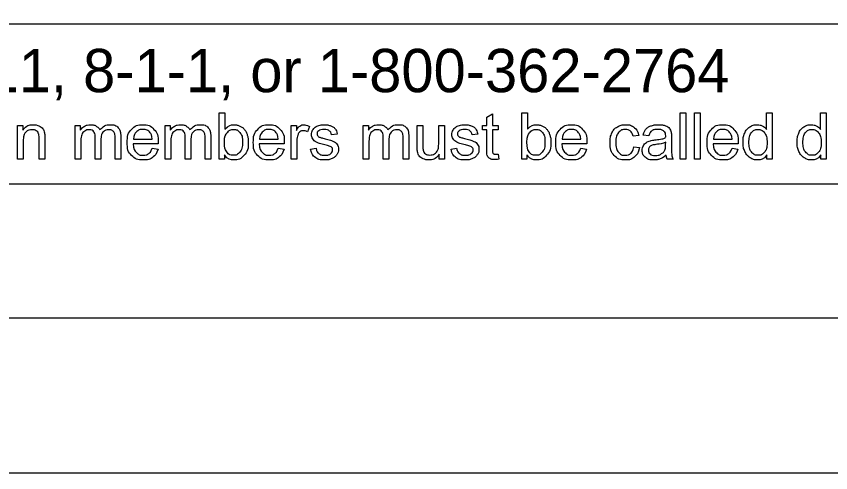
# Model space of a CAD drawing. Extents: x -1.2 to 34, y -8.5 to 22.
# Drawn here: x 15.565 to 18.2, y 0 to 1.476 of the extents above; entities that cross this region are included whole.
import ezdxf

# ---------------------------------------------------------------- set-up
doc = ezdxf.new("R2010")
doc.units = 0
for name, color, linetype in [('SH_Border', 7, 'Continuous'), ('SH_Cut_Line', 7, 'Continuous'), ('SH_Data', 7, 'Continuous'), ('SH_Text', 7, 'Continuous')]:
    doc.layers.add(name, color=color, linetype=linetype)

msp = doc.modelspace()

# ---------------------------------------------------------------- linework, layer by layer
at = {"layer": 'SH_Border'}
msp.add_lwpolyline([(1.5, 21.5), (33.5, 21.5), (33.5, 0.5), (1.5, 0.5)], close=True, dxfattribs=at)
at = {"layer": 'SH_Cut_Line'}
msp.add_lwpolyline([(0, 0), (34, 0), (34, 22), (0, 22)], close=True, dxfattribs=at)
at = {"layer": 'SH_Data'}
for p, q in [((19.0916, 1.4506), (14.8416, 1.4506)), ((19.0916, 0.9328), (14.8416, 0.9328))]:
    msp.add_line(p, q, dxfattribs=at)
at = {"layer": 'SH_Text'}
for points in [[(16.2384, 1.0139), (16.2214, 1.0139), (16.2214, 1.164), (16.2398, 1.164), (16.2398, 1.1105)], [(17.0874, 1.0457), (17.0874, 1.1084), (17.0737, 1.1084), (17.0737, 1.1227), (17.0874, 1.1227), (17.0874, 1.1497), (17.1058, 1.1607), (17.1058, 1.1227), (17.1242, 1.1227), (17.1242, 1.1084), (17.1058, 1.1084), (17.1058, 1.0447)], [(17.2175, 1.0139), (17.2004, 1.0139), (17.2004, 1.164), (17.2189, 1.164), (17.2189, 1.1105)], [(17.7131, 1.0139), (17.7131, 1.164), (17.7316, 1.164), (17.7316, 1.0139), (17.7131, 1.0139)], [(17.7597, 1.0139), (17.7597, 1.164), (17.7781, 1.164), (17.7781, 1.0139), (17.7597, 1.0139)], [(17.9926, 1.1102), (17.9926, 1.164), (18.011, 1.164), (18.011, 1.0139), (17.994, 1.0139)], [(18.1675, 1.1102), (18.1675, 1.164), (18.1859, 1.164), (18.1859, 1.0139), (18.1689, 1.0139)], [(15.5689, 1.0139), (15.5689, 1.1227), (15.5855, 1.1227), (15.5855, 1.1073)], [(15.7553, 1.0139), (15.7553, 1.1227), (15.7718, 1.1227), (15.7718, 1.1074)], [(16.0467, 1.0139), (16.0467, 1.1227), (16.0632, 1.1227), (16.0632, 1.1074)], [(16.4545, 1.0139), (16.4545, 1.1227), (16.4711, 1.1227), (16.4711, 1.1062)], [(16.5135, 1.1192), (16.5071, 1.1022)], [(16.6877, 1.0139), (16.6877, 1.1227), (16.7042, 1.1227), (16.7042, 1.1074)], [(16.862, 1.0553), (16.862, 1.1227), (16.8804, 1.1227), (16.8804, 1.0624)], [(16.9317, 1.0645), (16.9317, 1.1227), (16.9501, 1.1227), (16.9501, 1.0139), (16.9337, 1.0139)], [(15.6573, 1.0808), (15.6573, 1.0139), (15.6388, 1.0139), (15.6388, 1.08)], [(15.8384, 1.0771), (15.8384, 1.0139), (15.82, 1.0139), (15.82, 1.0845)], [(15.9028, 1.0886), (15.9028, 1.0139), (15.8844, 1.0139), (15.8844, 1.0824)], [(16.1298, 1.0771), (16.1298, 1.0139), (16.1114, 1.0139), (16.1114, 1.0845)], [(16.1942, 1.0886), (16.1942, 1.0139), (16.1758, 1.0139), (16.1758, 1.0824)], [(16.6035, 1.0946), (16.5854, 1.0922)], [(16.7708, 1.0771), (16.7708, 1.0139), (16.7524, 1.0139), (16.7524, 1.0845)], [(16.8352, 1.0886), (16.8352, 1.0139), (16.8168, 1.0139), (16.8168, 1.0824)], [(17.0581, 1.0946), (17.04, 1.0922)], [(17.5795, 1.0907), (17.5615, 1.0879)], [(17.612, 1.0892), (17.5939, 1.0916)], [(17.685, 1.084), (17.685, 1.0595)], [(15.5873, 1.0733), (15.5873, 1.0139), (15.5689, 1.0139)], [(15.7738, 1.0703), (15.7738, 1.0139), (15.7553, 1.0139)], [(16.0241, 1.0636), (15.9429, 1.0636)], [(15.944, 1.0787), (16.0047, 1.0787)], [(16.0651, 1.0703), (16.0651, 1.0139), (16.0467, 1.0139)], [(16.4321, 1.0636), (16.3509, 1.0636)], [(16.3519, 1.0787), (16.4127, 1.0787)], [(16.4729, 1.0709), (16.4729, 1.0139), (16.4545, 1.0139)], [(16.7061, 1.0703), (16.7061, 1.0139), (16.6877, 1.0139)], [(17.4111, 1.0636), (17.33, 1.0636)], [(17.331, 1.0787), (17.3918, 1.0787)], [(17.6663, 1.0617), (17.6664, 1.0685)], [(17.9007, 1.0636), (17.8196, 1.0636)], [(17.8206, 1.0787), (17.8814, 1.0787)], [(16.0045, 1.049), (16.0236, 1.0466)], [(16.4125, 1.049), (16.4316, 1.0466)], [(16.5171, 1.0464), (16.5353, 1.0492)], [(16.9337, 1.0139), (16.9337, 1.0299)], [(16.9717, 1.0464), (16.9899, 1.0492)], [(17.1242, 1.0303), (17.1268, 1.014)], [(17.3916, 1.049), (17.4106, 1.0466)], [(17.5631, 1.0537), (17.5812, 1.0513)], [(17.8812, 1.049), (17.9002, 1.0466)], [(16.2384, 1.0275), (16.2384, 1.0139)], [(17.2175, 1.0275), (17.2175, 1.0139)], [(17.6908, 1.0139), (17.6716, 1.0139)], [(17.994, 1.0139), (17.994, 1.0276)], [(18.1689, 1.0139), (18.1689, 1.0276)]]:
    msp.add_lwpolyline(points, dxfattribs=at)
for points, degree in [([(15.5855, 1.1073), (15.5975, 1.1251), (15.6201, 1.1251), (15.6299, 1.1251), (15.6382, 1.1216), (15.6464, 1.1181), (15.6505, 1.1123), (15.6546, 1.1066), (15.6562, 1.0987), (15.6573, 1.0936), (15.6573, 1.0808)], 3), ([(15.6388, 1.08), (15.6388, 1.0913), (15.6367, 1.0969), (15.6345, 1.1024), (15.6291, 1.1058), (15.6236, 1.1091), (15.6162, 1.1091), (15.6044, 1.1091), (15.5959, 1.1016), (15.5873, 1.0942), (15.5873, 1.0733)], 3), ([(15.7718, 1.1074), (15.7769, 1.1154), (15.7854, 1.1202), (15.7939, 1.1251), (15.8048, 1.1251), (15.8169, 1.1251), (15.8246, 1.1201), (15.8324, 1.1151), (15.8356, 1.106), (15.8485, 1.1251), (15.8692, 1.1251), (15.8854, 1.1251), (15.8941, 1.1162), (15.9028, 1.1072), (15.9028, 1.0886)], 3), ([(15.82, 1.0845), (15.82, 1.0968), (15.8155, 1.103), (15.811, 1.1091), (15.8007, 1.1091), (15.7929, 1.1091), (15.7863, 1.105), (15.7797, 1.1009), (15.7767, 1.093), (15.7738, 1.0851), (15.7738, 1.0703)], 3), ([(15.8844, 1.0824), (15.8844, 1.0934), (15.8826, 1.0983), (15.8808, 1.1032), (15.8761, 1.1061), (15.8714, 1.1091), (15.8651, 1.1091), (15.8536, 1.1091), (15.846, 1.1015), (15.8384, 1.0938), (15.8384, 1.0771)], 3), ([(16.0236, 1.0466), (16.0191, 1.0299), (16.0069, 1.0207), (15.9947, 1.0115), (15.9757, 1.0115), (15.9519, 1.0115), (15.9379, 1.0262), (15.9239, 1.0409), (15.9239, 1.0674), (15.9239, 1.0948), (15.9381, 1.11), (15.9522, 1.1251), (15.9747, 1.1251), (15.9965, 1.1251), (16.0104, 1.1103), (16.0242, 1.0954), (16.0242, 1.0685), (16.0242, 1.0668), (16.0241, 1.0636)], 3), ([(16.0047, 1.0787), (16.0035, 1.0924), (15.9978, 1.0993), (15.9889, 1.11), (15.9749, 1.11), (15.9622, 1.11), (15.9535, 1.1015), (15.9449, 1.093), (15.944, 1.0787)], 3), ([(16.0632, 1.1074), (16.0683, 1.1154), (16.0768, 1.1202), (16.0853, 1.1251), (16.0962, 1.1251), (16.1083, 1.1251), (16.116, 1.1201), (16.1237, 1.1151), (16.1269, 1.106), (16.1399, 1.1251), (16.1606, 1.1251), (16.1768, 1.1251), (16.1855, 1.1162), (16.1942, 1.1072), (16.1942, 1.0886)], 3), ([(16.1114, 1.0845), (16.1114, 1.0968), (16.1069, 1.103), (16.1023, 1.1091), (16.0921, 1.1091), (16.0843, 1.1091), (16.0777, 1.105), (16.0711, 1.1009), (16.0681, 1.093), (16.0651, 1.0851), (16.0651, 1.0703)], 3), ([(16.1758, 1.0824), (16.1758, 1.0934), (16.174, 1.0983), (16.1722, 1.1032), (16.1675, 1.1061), (16.1628, 1.1091), (16.1564, 1.1091), (16.145, 1.1091), (16.1374, 1.1015), (16.1298, 1.0938), (16.1298, 1.0771)], 3), ([(16.2382, 1.0691), (16.2382, 1.0495), (16.2435, 1.0408), (16.2522, 1.0266), (16.267, 1.0266), (16.2791, 1.0266), (16.2879, 1.0371), (16.2967, 1.0476), (16.2967, 1.0684), (16.2967, 1.0897), (16.2882, 1.0999), (16.2798, 1.11), (16.2678, 1.11), (16.2558, 1.11), (16.247, 1.0995), (16.2382, 1.089), (16.2382, 1.0691)], 3), ([(16.2398, 1.1105), (16.2515, 1.1251), (16.2696, 1.1251), (16.2796, 1.1251), (16.2886, 1.1211), (16.2975, 1.117), (16.3033, 1.1097), (16.3091, 1.1024), (16.3124, 1.0921), (16.3157, 1.0817), (16.3157, 1.0699), (16.3157, 1.042), (16.3018, 1.0267), (16.288, 1.0115), (16.2686, 1.0115), (16.2494, 1.0115), (16.2384, 1.0275)], 3), ([(16.4316, 1.0466), (16.427, 1.0299), (16.4149, 1.0207), (16.4027, 1.0115), (16.3837, 1.0115), (16.3599, 1.0115), (16.3459, 1.0262), (16.3319, 1.0409), (16.3319, 1.0674), (16.3319, 1.0948), (16.346, 1.11), (16.3602, 1.1251), (16.3827, 1.1251), (16.4045, 1.1251), (16.4183, 1.1103), (16.4322, 1.0954), (16.4322, 1.0685), (16.4322, 1.0668), (16.4321, 1.0636)], 3), ([(16.4127, 1.0787), (16.4115, 1.0924), (16.4057, 1.0993), (16.3969, 1.11), (16.3829, 1.11), (16.3702, 1.11), (16.3615, 1.1015), (16.3529, 1.093), (16.3519, 1.0787)], 3), ([(16.4711, 1.1062), (16.4774, 1.1178), (16.4828, 1.1214), (16.4882, 1.1251), (16.4946, 1.1251), (16.5039, 1.1251), (16.5135, 1.1192)], 3), ([(16.5854, 1.0922), (16.5842, 1.1006), (16.5783, 1.1053), (16.5724, 1.11), (16.5616, 1.11), (16.5489, 1.11), (16.5435, 1.1058), (16.538, 1.1016), (16.538, 1.096), (16.538, 1.0924), (16.5403, 1.0895), (16.5425, 1.0865), (16.5474, 1.0846), (16.5501, 1.0835), (16.5637, 1.0799), (16.5833, 1.0746), (16.591, 1.0713), (16.5988, 1.068), (16.6032, 1.0616), (16.6076, 1.0553), (16.6076, 1.0459), (16.6076, 1.0367), (16.6022, 1.0285), (16.5968, 1.0204), (16.5867, 1.0159), (16.5765, 1.0115), (16.5637, 1.0115), (16.5424, 1.0115), (16.5313, 1.0203), (16.5202, 1.0291), (16.5171, 1.0464)], 3), ([(16.5353, 1.0492), (16.5368, 1.0383), (16.5439, 1.0324), (16.5509, 1.0266), (16.5635, 1.0266), (16.5763, 1.0266), (16.5824, 1.0318), (16.5886, 1.0369), (16.5886, 1.0439), (16.5886, 1.0502), (16.5832, 1.0538), (16.5794, 1.0562), (16.5643, 1.06), (16.544, 1.0651), (16.5361, 1.0689), (16.5283, 1.0726), (16.5242, 1.0792), (16.5202, 1.0858), (16.5202, 1.0938), (16.5202, 1.1011), (16.5235, 1.1073), (16.5268, 1.1135), (16.5326, 1.1176), (16.5369, 1.1207), (16.5443, 1.1229), (16.5518, 1.1251), (16.5603, 1.1251), (16.5731, 1.1251), (16.5828, 1.1214), (16.5925, 1.1177), (16.5971, 1.1114), (16.6017, 1.1051), (16.6035, 1.0946)], 3), ([(16.7042, 1.1074), (16.7093, 1.1154), (16.7178, 1.1202), (16.7263, 1.1251), (16.7372, 1.1251), (16.7493, 1.1251), (16.757, 1.1201), (16.7647, 1.1151), (16.7679, 1.106), (16.7808, 1.1251), (16.8016, 1.1251), (16.8178, 1.1251), (16.8265, 1.1162), (16.8352, 1.1072), (16.8352, 1.0886)], 3), ([(16.7524, 1.0845), (16.7524, 1.0968), (16.7479, 1.103), (16.7433, 1.1091), (16.7331, 1.1091), (16.7253, 1.1091), (16.7187, 1.105), (16.7121, 1.1009), (16.7091, 1.093), (16.7061, 1.0851), (16.7061, 1.0703)], 3), ([(16.8168, 1.0824), (16.8168, 1.0934), (16.815, 1.0983), (16.8132, 1.1032), (16.8085, 1.1061), (16.8038, 1.1091), (16.7974, 1.1091), (16.786, 1.1091), (16.7784, 1.1015), (16.7708, 1.0938), (16.7708, 1.0771)], 3), ([(17.04, 1.0922), (17.0387, 1.1006), (17.0329, 1.1053), (17.027, 1.11), (17.0162, 1.11), (17.0035, 1.11), (16.998, 1.1058), (16.9926, 1.1016), (16.9926, 1.096), (16.9926, 1.0924), (16.9949, 1.0895), (16.9971, 1.0865), (17.0019, 1.0846), (17.0047, 1.0835), (17.0182, 1.0799), (17.0378, 1.0746), (17.0456, 1.0713), (17.0533, 1.068), (17.0578, 1.0616), (17.0622, 1.0553), (17.0622, 1.0459), (17.0622, 1.0367), (17.0568, 1.0285), (17.0514, 1.0204), (17.0412, 1.0159), (17.0311, 1.0115), (17.0183, 1.0115), (16.997, 1.0115), (16.9859, 1.0203), (16.9747, 1.0291), (16.9717, 1.0464)], 3), ([(16.9899, 1.0492), (16.9914, 1.0383), (16.9984, 1.0324), (17.0055, 1.0266), (17.0181, 1.0266), (17.0309, 1.0266), (17.037, 1.0318), (17.0432, 1.0369), (17.0432, 1.0439), (17.0432, 1.0502), (17.0377, 1.0538), (17.0339, 1.0562), (17.0189, 1.06), (16.9985, 1.0651), (16.9907, 1.0689), (16.9829, 1.0726), (16.9788, 1.0792), (16.9747, 1.0858), (16.9747, 1.0938), (16.9747, 1.1011), (16.9781, 1.1073), (16.9814, 1.1135), (16.9872, 1.1176), (16.9915, 1.1207), (16.9989, 1.1229), (17.0063, 1.1251), (17.0149, 1.1251), (17.0277, 1.1251), (17.0374, 1.1214), (17.0471, 1.1177), (17.0517, 1.1114), (17.0563, 1.1051), (17.0581, 1.0946)], 3), ([(17.2173, 1.0691), (17.2173, 1.0495), (17.2226, 1.0408), (17.2313, 1.0266), (17.2461, 1.0266), (17.2581, 1.0266), (17.2669, 1.0371), (17.2757, 1.0476), (17.2757, 1.0684), (17.2757, 1.0897), (17.2673, 1.0999), (17.2589, 1.11), (17.2469, 1.11), (17.2348, 1.11), (17.226, 1.0995), (17.2173, 1.089), (17.2173, 1.0691)], 3), ([(17.2189, 1.1105), (17.2305, 1.1251), (17.2487, 1.1251), (17.2587, 1.1251), (17.2676, 1.1211), (17.2766, 1.117), (17.2824, 1.1097), (17.2882, 1.1024), (17.2915, 1.0921), (17.2947, 1.0817), (17.2947, 1.0699), (17.2947, 1.042), (17.2809, 1.0267), (17.2671, 1.0115), (17.2477, 1.0115), (17.2284, 1.0115), (17.2175, 1.0275)], 3), ([(17.4106, 1.0466), (17.4061, 1.0299), (17.3939, 1.0207), (17.3817, 1.0115), (17.3628, 1.0115), (17.3389, 1.0115), (17.325, 1.0262), (17.311, 1.0409), (17.311, 1.0674), (17.311, 1.0948), (17.3251, 1.11), (17.3392, 1.1251), (17.3618, 1.1251), (17.3836, 1.1251), (17.3974, 1.1103), (17.4112, 1.0954), (17.4112, 1.0685), (17.4112, 1.0668), (17.4111, 1.0636)], 3), ([(17.3918, 1.0787), (17.3905, 1.0924), (17.3848, 1.0993), (17.376, 1.11), (17.362, 1.11), (17.3493, 1.11), (17.3406, 1.1015), (17.3319, 1.093), (17.331, 1.0787)], 3), ([(17.5812, 1.0513), (17.5782, 1.0326), (17.566, 1.022), (17.5537, 1.0115), (17.5359, 1.0115), (17.5136, 1.0115), (17.5, 1.0261), (17.4864, 1.0407), (17.4864, 1.0679), (17.4864, 1.0855), (17.4923, 1.0987), (17.4981, 1.1119), (17.51, 1.1185), (17.522, 1.1251), (17.536, 1.1251), (17.5537, 1.1251), (17.565, 1.1162), (17.5763, 1.1072), (17.5795, 1.0907)], 3), ([(17.5615, 1.0879), (17.5589, 1.0989), (17.5524, 1.1045), (17.5459, 1.11), (17.5367, 1.11), (17.5228, 1.11), (17.5141, 1.1), (17.5054, 1.09), (17.5054, 1.0684), (17.5054, 1.0465), (17.5138, 1.0365), (17.5222, 1.0266), (17.5357, 1.0266), (17.5466, 1.0266), (17.5539, 1.0332), (17.5612, 1.0399), (17.5631, 1.0537)], 3), ([(17.6679, 1.0273), (17.6576, 1.0186), (17.6482, 1.015), (17.6387, 1.0115), (17.6278, 1.0115), (17.6099, 1.0115), (17.6003, 1.0202), (17.5907, 1.029), (17.5907, 1.0426), (17.5907, 1.0506), (17.5943, 1.0572), (17.598, 1.0638), (17.6038, 1.0678), (17.6097, 1.0717), (17.6171, 1.0738), (17.6225, 1.0752), (17.6335, 1.0766), (17.6558, 1.0792), (17.6663, 1.0829), (17.6664, 1.0867), (17.6664, 1.0877), (17.6664, 1.099), (17.6612, 1.1036), (17.6542, 1.1099), (17.6403, 1.1099), (17.6273, 1.1099), (17.6211, 1.1053), (17.6149, 1.1008), (17.612, 1.0892)], 3), ([(17.5939, 1.0916), (17.5963, 1.1032), (17.602, 1.1103), (17.6076, 1.1174), (17.6182, 1.1213), (17.6289, 1.1251), (17.6429, 1.1251), (17.6568, 1.1251), (17.6655, 1.1218), (17.6742, 1.1186), (17.6783, 1.1136), (17.6824, 1.1086), (17.6841, 1.101), (17.685, 1.0963), (17.685, 1.084)], 3), ([(17.9002, 1.0466), (17.8957, 1.0299), (17.8835, 1.0207), (17.8713, 1.0115), (17.8524, 1.0115), (17.8285, 1.0115), (17.8146, 1.0262), (17.8006, 1.0409), (17.8006, 1.0674), (17.8006, 1.0948), (17.8147, 1.11), (17.8288, 1.1251), (17.8514, 1.1251), (17.8732, 1.1251), (17.887, 1.1103), (17.9008, 1.0954), (17.9008, 1.0685), (17.9008, 1.0668), (17.9007, 1.0636)], 3), ([(17.8814, 1.0787), (17.8801, 1.0924), (17.8744, 1.0993), (17.8656, 1.11), (17.8515, 1.11), (17.8388, 1.11), (17.8302, 1.1015), (17.8215, 1.093), (17.8206, 1.0787)], 3), ([(17.994, 1.0276), (17.9836, 1.0115), (17.9636, 1.0115), (17.9505, 1.0115), (17.9396, 1.0186), (17.9287, 1.0258), (17.9227, 1.0387), (17.9167, 1.0515), (17.9167, 1.0682), (17.9167, 1.0845), (17.9222, 1.0977), (17.9276, 1.111), (17.9384, 1.1181), (17.9493, 1.1251), (17.9626, 1.1251), (17.9725, 1.1251), (17.9801, 1.121), (17.9878, 1.1168), (17.9926, 1.1102)], 3), ([(17.9357, 1.0682), (17.9357, 1.0473), (17.9445, 1.0369), (17.9533, 1.0266), (17.9653, 1.0266), (17.9774, 1.0266), (17.9859, 1.0365), (17.9943, 1.0464), (17.9943, 1.0667), (17.9943, 1.089), (17.9857, 1.0994), (17.9771, 1.1099), (17.9645, 1.1099), (17.9522, 1.1099), (17.944, 1.0999), (17.9357, 1.0898), (17.9357, 1.0682)], 3), ([(18.1689, 1.0276), (18.1585, 1.0115), (18.1384, 1.0115), (18.1254, 1.0115), (18.1145, 1.0186), (18.1036, 1.0258), (18.0976, 1.0387), (18.0916, 1.0515), (18.0916, 1.0682), (18.0916, 1.0845), (18.097, 1.0977), (18.1024, 1.111), (18.1133, 1.1181), (18.1241, 1.1251), (18.1375, 1.1251), (18.1473, 1.1251), (18.155, 1.121), (18.1627, 1.1168), (18.1675, 1.1102)], 3), ([(18.1106, 1.0682), (18.1106, 1.0473), (18.1194, 1.0369), (18.1282, 1.0266), (18.1402, 1.0266), (18.1523, 1.0266), (18.1607, 1.0365), (18.1692, 1.0464), (18.1692, 1.0667), (18.1692, 1.089), (18.1606, 1.0994), (18.152, 1.1099), (18.1394, 1.1099), (18.1271, 1.1099), (18.1188, 1.0999), (18.1106, 1.0898), (18.1106, 1.0682)], 3), ([(16.5071, 1.1022), (16.5004, 1.1061), (16.4936, 1.1061), (16.4876, 1.1061), (16.4828, 1.1025), (16.478, 1.0988), (16.476, 1.0924), (16.4729, 1.0826), (16.4729, 1.0709)], 3), ([(15.9429, 1.0636), (15.9439, 1.0456), (15.9531, 1.0361), (15.9622, 1.0266), (15.9758, 1.0266), (15.986, 1.0266), (15.9931, 1.0319), (16.0003, 1.0373), (16.0045, 1.049)], 3), ([(16.3509, 1.0636), (16.3519, 1.0456), (16.3611, 1.0361), (16.3702, 1.0266), (16.3838, 1.0266), (16.394, 1.0266), (16.4011, 1.0319), (16.4083, 1.0373), (16.4125, 1.049)], 3), ([(16.9337, 1.0299), (16.921, 1.0115), (16.8992, 1.0115), (16.8896, 1.0115), (16.8812, 1.0152), (16.8729, 1.0189), (16.8688, 1.0244), (16.8648, 1.03), (16.8631, 1.0381), (16.862, 1.0435), (16.862, 1.0553)], 3), ([(16.8804, 1.0624), (16.8804, 1.048), (16.8816, 1.043), (16.8833, 1.0357), (16.8889, 1.0315), (16.8946, 1.0274), (16.9029, 1.0274), (16.9111, 1.0274), (16.9184, 1.0316), (16.9257, 1.0359), (16.9287, 1.0432), (16.9317, 1.0505), (16.9317, 1.0645)], 3), ([(17.33, 1.0636), (17.331, 1.0456), (17.3401, 1.0361), (17.3492, 1.0266), (17.3629, 1.0266), (17.373, 1.0266), (17.3802, 1.0319), (17.3874, 1.0373), (17.3916, 1.049)], 3), ([(17.6664, 1.0685), (17.6564, 1.0644), (17.6363, 1.0615), (17.6249, 1.0599), (17.6202, 1.0578), (17.6155, 1.0558), (17.6129, 1.0518), (17.6104, 1.0479), (17.6104, 1.0431), (17.6104, 1.0357), (17.6159, 1.0308), (17.6215, 1.0259), (17.6323, 1.0259), (17.6429, 1.0259), (17.6512, 1.0306), (17.6595, 1.0352), (17.6634, 1.0433), (17.6663, 1.0495), (17.6663, 1.0617)], 3), ([(17.685, 1.0595), (17.685, 1.0338), (17.6862, 1.027), (17.6873, 1.0201), (17.6908, 1.0139)], 3), ([(17.8196, 1.0636), (17.8206, 1.0456), (17.8297, 1.0361), (17.8388, 1.0266), (17.8525, 1.0266), (17.8626, 1.0266), (17.8698, 1.0319), (17.877, 1.0373), (17.8812, 1.049)], 3), ([(17.1268, 1.014), (17.1191, 1.0124), (17.1129, 1.0124), (17.1029, 1.0124), (17.0974, 1.0156), (17.0919, 1.0188), (17.0896, 1.0239), (17.0874, 1.0291), (17.0874, 1.0457)], 3), ([(17.1058, 1.0447), (17.1058, 1.0367), (17.1068, 1.0345), (17.1077, 1.0322), (17.1099, 1.0309), (17.1121, 1.0296), (17.1162, 1.0296), (17.1192, 1.0296), (17.1242, 1.0303)], 3), ([(17.6716, 1.0139), (17.6687, 1.0196), (17.6679, 1.0273)], 2)]:
    msp.add_open_spline(points, degree=degree, dxfattribs=at)

# ---------------------------------------------------------------- texts
msp.add_text('OHIO811, 8-1-1, or 1-800-362-2764', height=0.14, dxfattribs=at).set_placement((14.8861, 1.2306))

doc.saveas('drawing.dxf')
